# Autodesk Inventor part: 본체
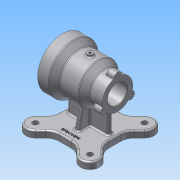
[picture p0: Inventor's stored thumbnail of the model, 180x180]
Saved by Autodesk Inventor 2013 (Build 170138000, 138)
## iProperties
Created: 2017-03
Part Number: 본체
Material: 알루미늄 6061
Document SubType Name: Modeling
Designer: Administrator
Density: 2.71 g/cm^3
Mass: 1008.17 g
Surface Area: 842.601 cm^2
Volume: 372.018 cm^3
Author: Administrator
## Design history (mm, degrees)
sketch "스케치1"
  geometry: L1 (50, 0)-(-50, 0); L2 (-50, 0)-(-50, 45); L3 (50, 27.5)-(27, 27.5); L4 (-30, 45)-(-19, 36); L5 (15, 36)-(27, 27.5); L6 (50, 27.5)-(50, 0); L7 (15, 36)-(-19, 36); L8 (-50, 45)-(-30, 45); L9 (-50, 0)-(-27, 0); L10 (-27, 0)-(-27, 35); L11 (-27, 35)-(-50, 35); L12 (-50, 35)-(-50, 0); L13 (-27, 0)-(20, 0); L14 (20, 0)-(20, 26); L15 (20, 26)-(-27, 26); L16 (-27, 26)-(-27, 0); L17 (20, 0)-(50, 0); L18 (50, 0)-(50, 17.5); L19 (50, 17.5)-(20, 17.5); L20 (20, 17.5)-(20, 0); 2 further points
  constraints: 40 end point, 10 parallel, 4 horizontal, 4 perpendicular, 1 coincident, 1 midpoint, 1 point on line
  dimensions: "d0" = 100 distance of L1.start L1.end; "d8" = 55 diameter of L3 L1; "d9" = 72 diameter of L7 L1; "d10" = 90 diameter of L8 L1; "d12" = 70 diameter of L11 L1; "d13" = 52 diameter of L15 L1; "d14" = 35 diameter of L19 L17; "d15" = 23 distance between parallel lines of L16 L2; "d16" = 47 distance between parallel lines of L14 L10; "d119" = 20 distance of L2.end L4.start; "d120" = 31 horizontal distance of L4.end L2.end; "d121" = 65 horizontal distance of L5.start L2.end; "d122" = 23 distance from line of L6 L3.end
revolve "회전2" sketch "스케치1" stored, may be unused: angle "d17" = 90 deg
chamfer "모따기1" distance "d18" = 1; stored, may be unused: second distance "d19" = 2, angle "d20" = 45 deg
fillet "모깎기1" dims "d21" = 3
node "작업 평면1"
sketch "스케치3"
  geometry: L1 (20.958, -45)-(-20.958, -45); L2 (-45, -20.958)-(-45, 20.958); L3 (-20.958, 45)-(20.958, 45); L4 (0, 0)-(82.902, 0); L5 (49.497, -49.497)-(66.497, -49.497); L6 (49.497, -49.497)-(66.497, -49.497); L7 (61.518, -37.477)-(45, -20.958); L8 (37.477, -61.518)-(20.958, -45); L9 (45, 20.958)-(45, -20.958); L10 (37.477, 61.518)-(20.958, 45); L11 (61.518, 37.477)-(45, 20.958); L12 (-61.518, 37.477)-(-45, 20.958); L13 (-37.477, 61.518)-(-20.958, 45); L14 (-37.477, -61.518)-(-20.958, -45); L15 (-61.518, -37.477)-(-45, -20.958); A1 r 17 centre (49.497, -49.497) between (37.477, -61.518) and (61.518, -37.477); A2 r 17 centre (49.497, 49.497) between (61.518, 37.477) and (37.477, 61.518); A3 r 17 centre (-49.497, 49.497) between (-37.477, 61.518) and (-61.518, 37.477); A4 r 17 centre (-49.497, -49.497) between (-61.518, -37.477) and (-37.477, -61.518); 2 further points
  constraints: 30 end point, 8 point on circle, 4 centre point, 4 horizontal, 3 parallel, 2 tangent, 1 coincident, 1 perpendicular, 33 other
  dimensions: "d25" = 45 distance from line of point (0, 0) L1; "d29" = 34 diameter of A1; "d34" = 360 deg dimension on point (0, 0) L5.start (derived)
extrude "돌출1" join sketch "스케치3" distance "d36" = 12; taper "d37" = 0 deg
fillet "모깎기2" dims "d38" = 25
hole "구멍1" diameter "d41" = 10; stored, may be unused: countersink angle "d45" = 90 deg, drill point angle "d47" = 118 deg; dims "d39" = 10, "d40" = 10, "d42" = 6, "d43" = 4, "d44" = 2, "d46" = 8
sketch "스케치4"
  geometry: L1 (-37, 4)-(37, 4); L2 (37, 4)-(37, -4); L3 (37, -4)-(-37, -4); L4 (-37, -4)-(-37, 4); L5 (-4, 25)-(4, 25); L6 (4, 25)-(4, -25); L7 (4, -25)-(-4, -25); L8 (-4, -25)-(-4, 25); 1 further point
  constraints: 16 end point, 4 parallel, 2 horizontal, 2 perpendicular
  dimensions: "d51" = 4 distance from line of point (0, 0) L1; "d52" = 8 distance of L3.end L1.start; "d53" = 4 distance from line of point (0, 0) L6; "d54" = 8 distance between parallel lines of L6 L8; "d55" = 74 distance of L1.start L1.end; "d56" = 37 distance from line of point (0, 0) L2; "d57" = 50 distance of L5.end L6.end; "d58" = 25 distance from line of L5 point (0, 0)
extrude "돌출2" join sketch "스케치4" stored distance "d59" = 12; taper "d60" = 0 deg
extrude "돌출3" join sketch "스케치4" stored distance "d61" = 12; taper "d62" = 0 deg
feature "면 기울기1" dims angle "d63" = 10 deg
feature "면 기울기2" dims angle "d64" = 10 deg
fillet "모깎기3" dims "d65" = 3
node "작업 평면2"
sketch "스케치5"
  geometry: C1 r 5 at (0, 0); 1 further point
  constraints: 1 centre point, 1 coincident
  dimensions: "d67" = 10 diameter of C1
extrude "돌출4" join sketch "스케치5" stored distance "d68" = 12; taper "d69" = 0 deg
fillet "모깎기4" dims "d70" = 3
hole "구멍2" diameter "d73" = 4.1; stored, may be unused: countersink angle "d77" = 90 deg, drill point angle "d79" = 118 deg; dims "d71" = 10, "d72" = 10, "d74" = 6, "d75" = 4, "d76" = 2, "d78" = 30
sketch "스케치6"
  geometry: A1 r 27.5 centre (0, 0) between (0, 27.5) and (-6.943, 26.609) reference; A2 r 7 centre (0, 27.5) between (6.943, 26.609) and (-6.943, 26.609)
  constraints: 5 point on circle, 1 centre point
  dimensions: "d80" = 14 diameter of A2
extrude "돌출5" join sketch "스케치6" distance "d81" = 15; taper "d82" = 0 deg
fillet "모깎기5" dims "d83" = 3
fillet "모깎기6" dims "d84" = 1
hole "구멍3" diameter "d87" = 3.2; stored, may be unused: countersink angle "d91" = 90 deg, drill point angle "d93" = 118 deg; dims "d88" = 9, "d89" = 4, "d90" = 2, "d92" = 11, "d94" = 10, "d95" = 10
fillet "모깎기7" dims "d99" = 3
sketch "스케치7"
  geometry: 1 further point
hole "구멍4" sketch "스케치7" at (0, 40) diameter "d101" = 3.2; stored, may be unused: countersink angle "d105" = 90 deg, drill point angle "d107" = 118 deg; dims "d102" = 9, "d103" = 4, "d104" = 2, "d106" = 11
node "작업 평면3"
sketch "스케치9"
  geometry: L1 (45, -10.603)-(45, 10.603) reference; 3 further points
  constraints: 1 coincident, 1 other
  dimensions: "d114" = 35 distance of point (0, 0) point (0, -35); "d115" = 45 distance from line of L1 point (0, -35)
feature "엠보싱1" sketch "스케치9" dims "d0" = 100, "d8" = 55, "d9" = 72, "d10" = 90, "d12" = 70, "d13" = 52, "d14" = 35, "d15" = 23, "d16" = 47, "d116" = 0.5, "d117" = 0, "d119" = 20, "d120" = 31, "d121" = 65, "d122" = 23
fillet "모깎기8" dims "d118" = 3
node "솔리드2"
pattern_circular "원형 패턴1" dims angle "d49" = 360 deg
pattern_circular "원형 패턴2" dims "d97" = 360 deg
pattern_circular "원형 패턴3" dims angle "d109" = 360 deg
other parameters: "d2" = 72, "d6" = 65, "d7" = 23, "d22" = -82, "d111" = 21.5
